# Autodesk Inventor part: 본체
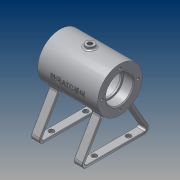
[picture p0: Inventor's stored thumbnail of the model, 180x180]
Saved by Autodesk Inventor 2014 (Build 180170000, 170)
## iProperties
Created: 2016-03
Part Number: 본체
Material: 알루미늄 6061
Document SubType Name: Modeling
Designer: SEC
Density: 2.71 g/cm^3
Appearance: 알루미늄 - 평지
Mass: 213.146 g
Surface Area: 333.935 cm^2
Volume: 78.6515 cm^3
Author: SEC
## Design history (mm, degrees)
sketch "스케치1"
  geometry: L1 (-35, 0)-(35, 0); L2 (-35, -16)-(-35, -26); L3 (-35, -26)-(35, -26); L4 (35, -26)-(35, -16); L5 (35, -16)-(23, -16); L6 (23, -16)-(23, -14); L7 (23, -14)-(21, -14); L8 (21, -14)-(21, -21); L9 (21, -21)-(-21, -21); L10 (-21, -21)-(-21, -14); L11 (-21, -14)-(-23, -14); L12 (-23, -14)-(-23, -16); L13 (-23, -16)-(-35, -16); 3 further points
  constraints: 26 end point, 10 parallel, 3 collinear, 3 vertical alignment, 2 midpoint, 2 perpendicular, 1 coincident, 1 horizontal
  dimensions: "d0" = 70 distance of L1.start L1.end; "d1" = 52 diameter of L3 L1; "d2" = 32 diameter of L13 L1; "d3" = 28 diameter of L11 L1; "d4" = 42 diameter of L9 L1; "d5" = 12 distance of L12.end L2.start; "d6" = 42 distance of L8.end L9.end
revolve "회전1" sketch "스케치1" stored, may be unused: angle "d7" = 90 deg
sketch "스케치2"
  geometry: 2 further points
  constraints: 1 vertical alignment
  dimensions: "d8" = 21 distance of point (0, 0) point (0, 21)
hole "구멍1" sketch "스케치2" at (0, 21) diameter "d9" = 3.242; stored, may be unused: countersink angle "d13" = 90 deg, drill point angle "d15" = 118 deg; dims "d10" = 8, "d11" = 4, "d12" = 2, "d14" = 10
fillet "모깎기1" dims "d19" = 0.3
chamfer "모따기1" distance "d20" = 1; stored, may be unused: second distance "d21" = 2, angle "d22" = 45 deg
node "작업 평면1"
sketch "스케치3"
  geometry: L1 (-16.613, -20)-(-38.264, -57.5); L2 (-33.934, -65)-(33.934, -65); L3 (38.264, -57.5)-(16.613, -20); L4 (0, 26)-(0, -26); L5 (14.183, -21.791)-(35.666, -59); L6 (33.934, -62)-(-33.934, -62); L7 (-35.666, -59)-(-14.183, -21.791); A1 r 26 centre (0, 0) between (-16.613, -20) and (16.613, -20) reference; A2 r 5 centre (-33.934, -60) between (-38.264, -57.5) and (-33.934, -65); A3 r 5 centre (33.934, -60) between (33.934, -65) and (38.264, -57.5); A4 r 2 centre (33.934, -60) between (33.934, -62) and (35.666, -59); A5 r 2 centre (-33.934, -60) between (-35.666, -59) and (-33.934, -62); 3 further points
  constraints: 14 end point, 14 point on circle, 4 centre point, 4 tangent, 2 midpoint, 1 coincident, 1 equal radius, 1 horizontal, 1 perpendicular, 1 vertical alignment, 2 other
  dimensions: "d24" = 30 deg angle of L1 L4; "d25" = 30 deg angle of L4 L3; "d26" = 45 distance from line of L2 L1.start; "d27" = 65 distance from line of L2 point (0, 0); "d28" = 5 radius of A2; "d29" = 3 distance between parallel lines of L2 L6; "d30" = 3 distance between parallel lines of L1 L7; "d31" = 3 distance between parallel lines of L3 L5
extrude "돌출1" join sketch "스케치3" distance "d32" = 10; taper "d33" = 0 deg
sketch "스케치4"
  geometry: L1 (-10, 0)-(-10, 67.868) reference; 3 further points
  constraints: 1 vertical alignment
  dimensions: "d34" = 20 vertical distance of point (-5, 53.934) point (20, 33.934); "d35" = 40 distance of point (-5, 13.934) point (-5, 53.934); "d36" = 5 distance from line of L1 point (-5, 53.934)
hole "구멍2" sketch "스케치4" at (-5, 53.934), (-5, 13.934) diameter "d37" = 6; stored, may be unused: countersink angle "d41" = 90 deg, drill point angle "d43" = 118 deg; dims "d38" = 8, "d39" = 4, "d40" = 2, "d42" = 10
node "작업 평면2"
sketch "스케치5"
  geometry: C1 r 5 at (0, 0); 1 further point
  constraints: 1 centre point, 1 coincident
  dimensions: "d45" = 10 diameter of C1
extrude "돌출2" join sketch "스케치5" stored distance "d46" = 10 (= d45); taper "d47" = 0 deg
sketch "스케치6"
  geometry: 2 further points
  constraints: 1 coincident
hole "구멍3" sketch "스케치6" at (0, 0) diameter "d48" = 5.188; stored, may be unused: countersink angle "d52" = 90 deg, drill point angle "d54" = 118 deg; dims "d49" = 8, "d50" = 4, "d51" = 2, "d53" = 10
node "작업 평면4"
  node "작업 평면3"
sketch "스케치7"
  geometry: C1 r 6 at (0, 0); 1 further point
  constraints: 1 centre point, 1 coincident
  dimensions: "d57" = 12 diameter of C1
extrude "돌출3" join sketch "스케치7" stored distance "d58" = 10; taper "d59" = 0 deg
sketch "스케치8"
  geometry: 2 further points
  constraints: 1 coincident
hole "구멍4" sketch "스케치8" at (0, 0) diameter "d60" = 5.188; stored, may be unused: countersink angle "d64" = 90 deg, drill point angle "d66" = 118 deg; dims "d61" = 8, "d62" = 4, "d63" = 2, "d65" = 10
node "작업 평면5"
sketch "스케치9"
  geometry: 2 further points
  constraints: 1 coincident, 1 other
feature "엠보싱1" sketch "스케치9" dims "d68" = 0.5, "d69" = 0
fillet "모깎기2" dims "d70" = 0.5
fillet "모깎기3" dims "d71" = 3
fillet "모깎기4" dims "d72" = 2
fillet "모깎기5" dims "d73" = 2
fillet "모깎기6" dims "d74" = 3
node "솔리드1"
pattern_circular "원형 패턴1" dims angle "d17" = 360 deg
mirror "대칭1"
mirror "대칭2"
other parameters: "d44" = 29, "d55" = -15 deg, "d56" = -29
